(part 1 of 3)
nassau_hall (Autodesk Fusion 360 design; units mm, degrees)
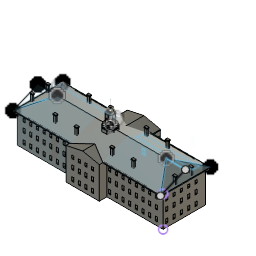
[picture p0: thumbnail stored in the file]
description: Open CASCADE Model
part number: Open CASCADE STEP translator 7.8 1
description: Part Number
part number: Open CASCADE STEP translator 7.8 1.1
part number: 2026-04-23-23-28-18-943
parameter "d279" = 0
base_feature "Base Feature1"
delete_face "DeleteFace1"
delete_face "DeleteFace2"
delete_face "DeleteFace3"
delete_face "DeleteFace4"
delete_face "DeleteFace5"
delete_face "DeleteFace6"
position "Position1"
extrude "Extrude1" add of existing geometry blind 100
extrude "Extrude2" add of existing geometry blind 2.5
extrude "Extrude3" add of existing geometry blind 2.5
extrude "Extrude4" add of existing geometry blind 2.5
extrude "Extrude5" add of existing geometry blind 2.5
extrude "Extrude6" add of existing geometry blind 2.5
extrude "Extrude7" add of existing geometry blind 2.5
sketch "Sketch1" plane through (-7.6571, 5.2611, 13.1142) normal (0, 1, 0) x axis (1, 0, 0)
split "Split1"
copy_paste_bodies "CopyPasteBodies1"
move "Move1"
move "Move2"
split "Split1"
extrude "Extrude1" add of existing geometry blind 92
delete_face "DeleteFace1"
delete_face "DeleteFace2"
extrude "Extrude8" add of existing geometry blind 30
extrude "Extrude9" add of existing geometry blind 1
extrude "Extrude2" add of existing geometry blind 30
split "Split2"
extrude "Extrude10" add of existing geometry blind 5
extrude "Extrude11" add of existing geometry blind 5
split "Split3"
move "Move1"
remove_body "RemoveBody1"
split "Split4"
delete_face "DeleteFace3"
split "Split5"
sketch "Sketch2" plane through (0, 0, 0) normal (0, 0, 1) x axis (1, 0, 0)
sketch "Sketch3" plane through (0, 0, 0) normal (0, 0, 1) x axis (1, 0, 0)
sketch "Sketch4" plane through (0, 0, 0) normal (0, 0, 1) x axis (1, 0, 0)
  line L1 (269.0284, 15.4255) -> (242.8779, 8.6742)
  line L2 (276.2569, 41.4481) -> (269.0284, 15.4255)
  line L3 (257.3349, 60.7195) -> (276.2569, 41.4481)
  line L4 (231.1844, 53.9682) -> (257.3349, 60.7195)
  line L5 (223.9559, 27.9456) -> (231.1844, 53.9682)
  line L6 (242.8779, 8.6742) -> (223.9559, 27.9456)
sketch "Sketch5" plane through (0, 0, 0) normal (0, 0, 1) x axis (1, 0, 0)
  line L1 (251.8031, 71.6805) -> (256.2642, 61.9825)
  line L2 (241.7911, 75.3836) -> (251.8031, 71.6805)
  line L3 (232.093, 70.9224) -> (241.7911, 75.3836)
  line L4 (228.39, 60.9104) -> (232.093, 70.9224)
  line L5 (232.8511, 51.2123) -> (228.39, 60.9104)
  line L6 (242.8632, 47.5093) -> (232.8511, 51.2123)
  line L7 (252.5612, 51.9704) -> (242.8632, 47.5093)
  line L8 (256.2642, 61.9825) -> (252.5612, 51.9704)
extrude "Extrude12" cut of existing geometry blind -80
extrude "Extrude5" cut of existing geometry blind -80
extrude "Extrude13" add of existing geometry blind 25
extrude "Extrude14" add of existing geometry blind 25
extrude "Extrude15" add of existing geometry blind 25
extrude "Extrude16" add of existing geometry blind 25
extrude "Extrude17" add of existing geometry blind 25
extrude "Extrude18" add of existing geometry blind 25
sketch "Sketch6" plane through (0, 19.3945, 0) normal (0, 1, 0) x axis (-1, 0, 0)
  line L1 (167.5476, -14.3624) -> (41.0476, -14.3624)
  line L2 (167.5476, 55.1376) -> (167.5476, -14.3624)
  line L3 (164.5476, 55.1376) -> (167.5476, 55.1376)
  line L4 (137.5476, 55.1376) -> (164.5476, 55.1376)
  line L5 (137.5476, 57.1376) -> (137.5476, 55.1376)
  line L6 (41.0476, 57.1376) -> (137.5476, 57.1376)
  line L7 (41.0476, -14.3624) -> (41.0476, 57.1376)
  line L8 (49.5073, 26) -> (45, 26)
  line L9 (49.5073, 17) -> (49.5073, 26)
  line L10 (45, 17) -> (49.5073, 17)
  line L11 (45, 26) -> (45, 17)
  horizontal L8
  vertical L9
  horizontal L10
  vertical L11
extrude "Extrude19" cut sketch "Sketch6" profile of L8 L9 L10 L11 against normal blind 15
sketch "Sketch7" plane through (0, 4.3945, 0) normal (0, 1, 0) x axis (-1, 0, 0)
  line L1 (49.5073, 17) -> (45, 17)
  line L2 (49.5073, 26) -> (49.5073, 17)
  line L3 (45, 26) -> (49.5073, 26)
  line L4 (45, 17) -> (45, 26)
sketch "Sketch8" plane through (0, 19.3945, 0) normal (0, 1, 0) x axis (-1, 0, 0)
  line L1 (49.5073, 17) -> (49.5073, 26)
  line L2 (45, 17) -> (49.5073, 17)
  line L3 (45, 26) -> (45, 17)
  line L4 (49.5073, 26) -> (45, 26)
  line L5 (167.5476, -14.3624) -> (41.0476, -14.3624)
  line L6 (167.5476, 55.1376) -> (167.5476, -14.3624)
  line L7 (164.5476, 55.1376) -> (167.5476, 55.1376)
  line L8 (137.5476, 55.1376) -> (164.5476, 55.1376)
  line L9 (137.5476, 57.1376) -> (137.5476, 55.1376)
  line L10 (41.0476, 57.1376) -> (137.5476, 57.1376)
  line L11 (41.0476, -14.3624) -> (41.0476, 57.1376)
  line L12 (49.5133, 3) -> (45, 3)
  line L13 (49.5133, -6) -> (49.5133, 3)
  line L14 (45, -6) -> (49.5133, -6)
  line L15 (45, 3) -> (45, -6)
  horizontal L12
  vertical L13
  horizontal L14
  vertical L15
sketch "Sketch9" plane through (0, 19.3945, 0) normal (0, 1, 0) x axis (-1, 0, 0)
sketch "Sketch10" plane through (0, 19.3945, 0) normal (0, 1, 0) x axis (-1, 0, 0)
  line L1 (64.5, 3) -> (60, 3)
  line L2 (64.5, -6) -> (64.5, 3)
  line L3 (60, -6) -> (64.5, -6)
  line L4 (60, 3) -> (60, -6)
  line L5 (79.5, 3) -> (75, 3)
  line L6 (79.5, -6) -> (79.5, 3)
  line L7 (75, -6) -> (79.5, -6)
  line L8 (75, 3) -> (75, -6)
  line L9 (94.5, 3) -> (90, 3)
  line L10 (94.5, -6) -> (94.5, 3)
  line L11 (90, -6) -> (94.5, -6)
  line L12 (90, 3) -> (90, -6)
  line L13 (109.5, 3) -> (105, 3)
  line L14 (109.5, -6) -> (109.5, 3)
  line L15 (105, -6) -> (109.5, -6)
  line L16 (105, 3) -> (105, -6)
  line L17 (124.5, 3) -> (120, 3)
  line L18 (124.5, -6) -> (124.5, 3)
  line L19 (120, -6) -> (124.5, -6)
  line L20 (120, 3) -> (120, -6)
  line L21 (139.5, 3) -> (135, 3)
  line L22 (139.5, -6) -> (139.5, 3)
  line L23 (135, -6) -> (139.5, -6)
  line L24 (135, 3) -> (135, -6)
  line L25 (154.5, 3) -> (150, 3)
  line L26 (154.5, -6) -> (154.5, 3)
  line L27 (150, -6) -> (154.5, -6)
  line L28 (150, 3) -> (150, -6)
  line L29 (64.5, 26) -> (60, 26)
  line L30 (64.5, 17) -> (64.5, 26)
  line L31 (60, 17) -> (64.5, 17)
  line L32 (60, 26) -> (60, 17)
  line L33 (79.5, 26) -> (75, 26)
  line L34 (79.5, 17) -> (79.5, 26)
  line L35 (75, 17) -> (79.5, 17)
  line L36 (75, 26) -> (75, 17)
  line L37 (94.5, 26) -> (90, 26)
  line L38 (94.5, 17) -> (94.5, 26)
  line L39 (90, 17) -> (94.5, 17)
  line L40 (90, 26) -> (90, 17)
  line L41 (109.5, 26) -> (105, 26)
  line L42 (109.5, 17) -> (109.5, 26)
  line L43 (105, 17) -> (109.5, 17)
  line L44 (105, 26) -> (105, 17)
  line L45 (124.5, 26) -> (120, 26)
  line L46 (124.5, 17) -> (124.5, 26)
  line L47 (120, 17) -> (124.5, 17)
  line L48 (120, 26) -> (120, 17)
  line L49 (139.5, 26) -> (135, 26)
  line L50 (139.5, 17) -> (139.5, 26)
  line L51 (135, 17) -> (139.5, 17)
  line L52 (135, 26) -> (135, 17)
  line L53 (154.5, 26) -> (150, 26)
  line L54 (154.5, 17) -> (154.5, 26)
  line L55 (150, 17) -> (154.5, 17)
  line L56 (150, 26) -> (150, 17)
  horizontal L1
  vertical L2
  horizontal L3
  vertical L4
  horizontal L5
  vertical L6
  horizontal L7
  vertical L8
  horizontal L9
  vertical L10
  horizontal L11
  vertical L12
  horizontal L13
  vertical L14
  horizontal L15
  vertical L16
  horizontal L17
  vertical L18
  horizontal L19
  vertical L20
  horizontal L21
  vertical L22
  horizontal L23
  vertical L24
  horizontal L25
  vertical L26
  horizontal L27
  vertical L28
  horizontal L29
  vertical L30
  horizontal L31
  vertical L32
  horizontal L33
  vertical L34
  horizontal L35
  vertical L36
  horizontal L37
  vertical L38
  horizontal L39
  vertical L40
  horizontal L41
  vertical L42
  horizontal L43
  vertical L44
  horizontal L45
  vertical L46
  horizontal L47
  vertical L48
  horizontal L49
  vertical L50
  horizontal L51
  vertical L52
  horizontal L53
  vertical L54
  horizontal L55
  vertical L56
extrude "Extrude20" cut sketch "Sketch10" + "Sketch8" profile of S2:L1 S2:L2 S2:L3 S2:L4 S2:L12 S2:L13 S2:L14 S2:L15 S1:L1 S1:L2 S1:L3 S1:L4 S1:L5 S1:L6 S1:L7 S1:L8 S1:L9 S1:L10 S1:L11 S1:L12 S1:L13 S1:L14 S1:L15 S1:L16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 blind -13
extrude "Extrude21" cut of existing geometry blind -13
sketch "Sketch11" plane through (0, 19.3945, 0) normal (0, 1, 0) x axis (-1, 0, 0)
  line L1 (49.5133, -6) -> (49.5133, 3)
  line L2 (45, -6) -> (49.5133, -6)
  line L3 (45, 3) -> (45, -6)
  line L4 (49.5133, 3) -> (45, 3)
  line L5 (154.5, -6) -> (154.5, 3)
  line L6 (150, -6) -> (154.5, -6)
  line L7 (150, 3) -> (150, -6)
  line L8 (154.5, 3) -> (150, 3)
  line L9 (109.5, 17) -> (109.5, 26)
  line L10 (105, 17) -> (109.5, 17)
  line L11 (105, 26) -> (105, 17)
  line L12 (109.5, 26) -> (105, 26)
  line L13 (79.5, -6) -> (79.5, 3)
  line L14 (75, -6) -> (79.5, -6)
  line L15 (75, 3) -> (75, -6)
  line L16 (79.5, 3) -> (75, 3)
  line L17 (64.5, 17) -> (64.5, 26)
  line L18 (60, 17) -> (64.5, 17)
  line L19 (60, 26) -> (60, 17)
  line L20 (64.5, 26) -> (60, 26)
  line L21 (94.5, 17) -> (94.5, 26)
  line L22 (90, 17) -> (94.5, 17)
  line L23 (90, 26) -> (90, 17)
  line L24 (94.5, 26) -> (90, 26)
  line L25 (124.5, 17) -> (124.5, 26)
  line L26 (120, 17) -> (124.5, 17)
  line L27 (120, 26) -> (120, 17)
  line L28 (124.5, 26) -> (120, 26)
  line L29 (124.5, -6) -> (124.5, 3)
  line L30 (120, -6) -> (124.5, -6)
  line L31 (120, 3) -> (120, -6)
  line L32 (124.5, 3) -> (120, 3)
  line L33 (154.5, 17) -> (154.5, 26)
  line L34 (150, 17) -> (154.5, 17)
  line L35 (150, 26) -> (150, 17)
  line L36 (154.5, 26) -> (150, 26)
  line L37 (109.5, -6) -> (109.5, 3)
  line L38 (105, -6) -> (109.5, -6)
  line L39 (105, 3) -> (105, -6)
  line L40 (109.5, 3) -> (105, 3)
  line L41 (79.5, 17) -> (79.5, 26)
  line L42 (75, 17) -> (79.5, 17)
  line L43 (75, 26) -> (75, 17)
  line L44 (79.5, 26) -> (75, 26)
  line L45 (64.5, -6) -> (64.5, 3)
  line L46 (60, -6) -> (64.5, -6)
  line L47 (60, 3) -> (60, -6)
  line L48 (64.5, 3) -> (60, 3)
  line L49 (94.5, -6) -> (94.5, 3)
  line L50 (90, -6) -> (94.5, -6)
  line L51 (90, 3) -> (90, -6)
  line L52 (94.5, 3) -> (90, 3)
  line L53 (139.5, 17) -> (139.5, 26)
  line L54 (135, 17) -> (139.5, 17)
  line L55 (135, 26) -> (135, 17)
  line L56 (139.5, 26) -> (135, 26)
  line L57 (139.5, -6) -> (139.5, 3)
  line L58 (135, -6) -> (139.5, -6)
  line L59 (135, 3) -> (135, -6)
  line L60 (139.5, 3) -> (135, 3)
  line L61 (49.5073, 17) -> (49.5073, 26)
  line L62 (45, 17) -> (49.5073, 17)
  line L63 (45, 26) -> (45, 17)
  line L64 (49.5073, 26) -> (45, 26)
  line L65 (167.5476, -14.3624) -> (41.0476, -14.3624)
  line L66 (167.5476, 55.1376) -> (167.5476, -14.3624)
  line L67 (164.5476, 55.1376) -> (167.5476, 55.1376)
  line L68 (137.5476, 55.1376) -> (164.5476, 55.1376)
  line L69 (137.5476, 57.1376) -> (137.5476, 55.1376)
  line L70 (41.0476, 57.1376) -> (137.5476, 57.1376)
  line L71 (41.0476, -14.3624) -> (41.0476, 57.1376)
  line L72 (49.5, 45) -> (45, 45)
  line L73 (49.5, 38) -> (49.5, 45)
  line L74 (45, 38) -> (49.5, 38)
  line L75 (45, 45) -> (45, 38)
  line L76 (64.5, 45) -> (60, 45)
  line L77 (64.5, 38) -> (64.5, 45)
  line L78 (60, 38) -> (64.5, 38)
  line L79 (60, 45) -> (60, 38)
  line L80 (79.5, 45) -> (75, 45)
  line L81 (79.5, 38) -> (79.5, 45)
  line L82 (75, 38) -> (79.5, 38)
  line L83 (75, 45) -> (75, 38)
  line L84 (94.5, 45) -> (90, 45)
  line L85 (94.5, 38) -> (94.5, 45)
  line L86 (90, 38) -> (94.5, 38)
  line L87 (90, 45) -> (90, 38)
  line L88 (109.5, 45) -> (105, 45)
  line L89 (109.5, 38) -> (109.5, 45)
  line L90 (105, 38) -> (109.5, 38)
  line L91 (105, 45) -> (105, 38)
  line L92 (124.5, 45) -> (120, 45)
  line L93 (124.5, 38) -> (124.5, 45)
  line L94 (120, 38) -> (124.5, 38)
  line L95 (120, 45) -> (120, 38)
  line L96 (139.5, 45) -> (135, 45)
  line L97 (139.5, 38) -> (139.5, 45)
  line L98 (135, 38) -> (139.5, 38)
  line L99 (135, 45) -> (135, 38)
  line L100 (154.5, 45) -> (150, 45)
  line L101 (154.5, 38) -> (154.5, 45)
  line L102 (150, 38) -> (154.5, 38)
  line L103 (150, 45) -> (150, 38)
  horizontal L72
  vertical L73
  horizontal L74
  vertical L75
  horizontal L76
  vertical L77
  horizontal L78
  vertical L79
  horizontal L80
  vertical L81
  horizontal L82
  vertical L83
  horizontal L84
  vertical L85
  horizontal L86
  vertical L87
  horizontal L88
  vertical L89
  horizontal L90
  vertical L91
  horizontal L92
  vertical L93
  horizontal L94
  vertical L95
  horizontal L96
  vertical L97
  horizontal L98
  vertical L99
  horizontal L100
  vertical L101
  horizontal L102
  vertical L103
extrude "Extrude22" cut sketch "Sketch11" profile of L72 L73 L74 L75 L76 L77 L78 L79 L80 L81 L82 L83 L84 L85 L86 L87 L88 L89 L90 L91 L92 L93 L94 L95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 against normal blind 13
extrude "Extrude23" cut of existing geometry blind -4
extrude "Extrude24" add of existing geometry blind 20
sketch "Sketch12" plane through (-167.5476, 0, 0) normal (-1, 0, 0) x axis (0, -1, 0)
  line L1 (63.1055, -14.3624) -> (-19.3945, -14.3624)
  line L2 (63.1055, 55.1376) -> (63.1055, -14.3624)
  line L3 (-19.3945, 55.1376) -> (63.1055, 55.1376)
  line L4 (-19.3945, -14.3624) -> (-19.3945, 55.1376)
  line L5 (-8.5, 45) -> (-13, 45)
  line L6 (-8.5, 38) -> (-8.5, 45)
  line L7 (-13, 38) -> (-8.5, 38)
  line L8 (-13, 45) -> (-13, 38)
  line L9 (6.5, 45) -> (2, 45)
  line L10 (6.5, 38) -> (6.5, 45)
  line L11 (2, 38) -> (6.5, 38)
  line L12 (2, 45) -> (2, 38)
  line L13 (21.5, 45) -> (17, 45)
  line L14 (21.5, 38) -> (21.5, 45)
  line L15 (17, 38) -> (21.5, 38)
  line L16 (17, 45) -> (17, 38)
  line L17 (36.5, 45) -> (32, 45)
  line L18 (36.5, 38) -> (36.5, 45)
  line L19 (32, 38) -> (36.5, 38)
  line L20 (32, 45) -> (32, 38)
  line L21 (51.5, 45) -> (47, 45)
  line L22 (51.5, 38) -> (51.5, 45)
  line L23 (47, 38) -> (51.5, 38)
  line L24 (47, 45) -> (47, 38)
  line L25 (-8.5, 26) -> (-13, 26)
  line L26 (-8.5, 17) -> (-8.5, 26)
  line L27 (-13, 17) -> (-8.5, 17)
  line L28 (-13, 26) -> (-13, 17)
  line L29 (6.5, 26) -> (2, 26)
  line L30 (6.5, 17) -> (6.5, 26)
  line L31 (2, 17) -> (6.5, 17)
  line L32 (2, 26) -> (2, 17)
  line L33 (21.5, 26) -> (17, 26)
  line L34 (21.5, 17) -> (21.5, 26)
  line L35 (17, 17) -> (21.5, 17)
  line L36 (17, 26) -> (17, 17)
  line L37 (36.5, 26) -> (32, 26)
  line L38 (36.5, 17) -> (36.5, 26)
  line L39 (32, 17) -> (36.5, 17)
  line L40 (32, 26) -> (32, 17)
  line L41 (51.5, 26) -> (47, 26)
  line L42 (51.5, 17) -> (51.5, 26)
  line L43 (47, 17) -> (51.5, 17)
  line L44 (47, 26) -> (47, 17)
  horizontal L5
  vertical L6
  horizontal L7
  vertical L8
  horizontal L9
  vertical L10
  horizontal L11
  vertical L12
  horizontal L13
  vertical L14
  horizontal L15
  vertical L16
  horizontal L17
  vertical L18
  horizontal L19
  vertical L20
  horizontal L21
  vertical L22
  horizontal L23
  vertical L24
  horizontal L25
  vertical L26
  horizontal L27
  vertical L28
  horizontal L29
  vertical L30
  horizontal L31
  vertical L32
  horizontal L33
  vertical L34
  horizontal L35
  vertical L36
  horizontal L37
  vertical L38
  horizontal L39
  vertical L40
  horizontal L41
  vertical L42
  horizontal L43
  vertical L44
sketch "Sketch13" plane through (-167.5476, 0, 0) normal (-1, 0, 0) x axis (0, -1, 0)
  line L1 (-8.5, 3) -> (-13, 3)
  line L2 (-8.5, -6) -> (-8.5, 3)
  line L3 (-13, -6) -> (-8.5, -6)
  line L4 (-13, 3) -> (-13, -6)
  line L5 (6.5, 3) -> (2, 3)
  line L6 (6.5, -6) -> (6.5, 3)
  line L7 (2, -6) -> (6.5, -6)
  line L8 (2, 3) -> (2, -6)
  line L9 (21.5, 3) -> (17, 3)
  line L10 (21.5, -6) -> (21.5, 3)
  line L11 (17, -6) -> (21.5, -6)
  line L12 (17, 3) -> (17, -6)
  line L13 (36.5, 3) -> (32, 3)
  line L14 (36.5, -6) -> (36.5, 3)
  line L15 (32, -6) -> (36.5, -6)
  line L16 (32, 3) -> (32, -6)
  line L17 (51.5, 3) -> (47, 3)
  line L18 (51.5, -6) -> (51.5, 3)
  line L19 (47, -6) -> (51.5, -6)
  line L20 (47, 3) -> (47, -6)
  horizontal L1
  vertical L2
  horizontal L3
  vertical L4
  horizontal L5
  vertical L6
  horizontal L7
  vertical L8
  horizontal L9
  vertical L10
  horizontal L11
  vertical L12
  horizontal L13
  vertical L14
  horizontal L15
  vertical L16
  horizontal L17
  vertical L18
  horizontal L19
  vertical L20
extrude "Extrude25" cut sketch "Sketch12" + "Sketch13" profile of S1:L5 S1:L6 S1:L7 S1:L8 S1:L9 S1:L10 S1:L11 S1:L12 S1:L13 S1:L14 S1:L15 S1:L16 S1:L17 S1:L18 S1:L19 S1:L20 S1:L21 S1:L22 S1:L23 S1:L24 S1:L25 S1:L26 S1:L27 S1:L28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 blind -13
extrude "Extrude26" add of existing geometry blind 4
extrude "Extrude27" add of existing geometry blind 4
extrude "Extrude28" add of existing geometry blind 2
sketch "Sketch14" plane through (0, 19.3945, 0) normal (0, 1, 0) x axis (-1, 0, 0)
  line L1 (-33.9524, -14.3624) -> (-160.4524, -14.3624)
  line L2 (-33.9524, 57.1376) -> (-33.9524, -14.3624)
  line L3 (-130.4524, 57.1376) -> (-33.9524, 57.1376)
  line L4 (-130.4524, 55.1376) -> (-130.4524, 57.1376)
  line L5 (-160.4524, 55.1376) -> (-130.4524, 55.1376)
  line L6 (-160.4524, -14.3624) -> (-160.4524, 55.1376)
  line L7 (-42.5, 45) -> (-38, 45)
  line L8 (-42.5, 38) -> (-42.5, 45)
  line L9 (-38, 38) -> (-42.5, 38)
  line L10 (-38, 45) -> (-38, 38)
  line L11 (-57.5, 45) -> (-53, 45)
  line L12 (-57.5, 38) -> (-57.5, 45)
  line L13 (-53, 38) -> (-57.5, 38)
  line L14 (-53, 45) -> (-53, 38)
  line L15 (-72.5, 45) -> (-68, 45)
  line L16 (-72.5, 38) -> (-72.5, 45)
  line L17 (-68, 38) -> (-72.5, 38)
  line L18 (-68, 45) -> (-68, 38)
  line L19 (-87.5, 45) -> (-83, 45)
  line L20 (-87.5, 38) -> (-87.5, 45)
  line L21 (-83, 38) -> (-87.5, 38)
  line L22 (-83, 45) -> (-83, 38)
  line L23 (-102.5, 45) -> (-98, 45)
  line L24 (-102.5, 38) -> (-102.5, 45)
  line L25 (-98, 38) -> (-102.5, 38)
  line L26 (-98, 45) -> (-98, 38)
  line L27 (-117.5, 45) -> (-113, 45)
  line L28 (-117.5, 38) -> (-117.5, 45)
  line L29 (-113, 38) -> (-117.5, 38)
  line L30 (-113, 45) -> (-113, 38)
  line L31 (-132.5, 45) -> (-128, 45)
  line L32 (-132.5, 38) -> (-132.5, 45)
  line L33 (-128, 38) -> (-132.5, 38)
  line L34 (-128, 45) -> (-128, 38)
  line L35 (-147.5, 45) -> (-143, 45)
  line L36 (-147.5, 38) -> (-147.5, 45)
  line L37 (-143, 38) -> (-147.5, 38)
  line L38 (-143, 45) -> (-143, 38)
  line L39 (-42.5, 26) -> (-38, 26)
  line L40 (-42.5, 17) -> (-42.5, 26)
  line L41 (-38, 17) -> (-42.5, 17)
  line L42 (-38, 26) -> (-38, 17)
  line L43 (-57.5, 26) -> (-53, 26)
  line L44 (-57.5, 17) -> (-57.5, 26)
  line L45 (-53, 17) -> (-57.5, 17)
  line L46 (-53, 26) -> (-53, 17)
  line L47 (-72.5, 26) -> (-68, 26)
  line L48 (-72.5, 17) -> (-72.5, 26)
  line L49 (-68, 17) -> (-72.5, 17)
  line L50 (-68, 26) -> (-68, 17)
  line L51 (-87.5, 26) -> (-83, 26)
  line L52 (-87.5, 17) -> (-87.5, 26)
  line L53 (-83, 17) -> (-87.5, 17)
  line L54 (-83, 26) -> (-83, 17)
  line L55 (-102.5, 26) -> (-98, 26)
  line L56 (-102.5, 17) -> (-102.5, 26)
  line L57 (-98, 17) -> (-102.5, 17)
  line L58 (-98, 26) -> (-98, 17)
  line L59 (-117.5, 26) -> (-113, 26)
  line L60 (-117.5, 16.9958) -> (-117.5, 26)
  line L61 (-113, 16.9958) -> (-117.5, 16.9958)
  line L62 (-113, 26) -> (-113, 16.9958)
  horizontal L7
  vertical L8
  horizontal L9
  vertical L10
  horizontal L11
  vertical L12
  horizontal L13
  vertical L14
  horizontal L15
  vertical L16
  horizontal L17
  vertical L18
  horizontal L19
  vertical L20
  horizontal L21
  vertical L22
  horizontal L23
  vertical L24
  horizontal L25
  vertical L26
  horizontal L27
  vertical L28
  horizontal L29
  vertical L30
  horizontal L31
  vertical L32
  horizontal L33
  vertical L34
  horizontal L35
  vertical L36
  horizontal L37
  vertical L38
  horizontal L39
  vertical L40
  horizontal L41
  vertical L42
  horizontal L43
  vertical L44
  horizontal L45
  vertical L46
  horizontal L47
  vertical L48
  horizontal L49
  vertical L50
  horizontal L51
  vertical L52
  horizontal L53
  vertical L54
  horizontal L55
  vertical L56
  horizontal L57
  vertical L58
  horizontal L59
  vertical L60
  horizontal L61
  vertical L62
sketch "Sketch15" plane through (0, 19.3945, 0) normal (0, 1, 0) x axis (-1, 0, 0)
  line L1 (-132.5, 26) -> (-128, 26)
  line L2 (-132.5, 17) -> (-132.5, 26)
  line L3 (-128, 17) -> (-132.5, 17)
  line L4 (-128, 26) -> (-128, 17)
  line L5 (-147.5, 26) -> (-143, 26)
  line L6 (-147.5, 17) -> (-147.5, 26)
  line L7 (-143, 17) -> (-147.5, 17)
  line L8 (-143, 26) -> (-143, 17)
  line L9 (-42.5323, 3) -> (-38, 3)
  line L10 (-42.5323, -6.0191) -> (-42.5323, 3)
  line L11 (-38, -6.0191) -> (-42.5323, -6.0191)
  line L12 (-38, 3) -> (-38, -6.0191)
  line L13 (-57.5, 3) -> (-53, 3)
  line L14 (-57.5, -6) -> (-57.5, 3)
  line L15 (-53, -6) -> (-57.5, -6)
  line L16 (-53, 3) -> (-53, -6)
  line L17 (-72.5, 3) -> (-68, 3)
  line L18 (-72.5, -6) -> (-72.5, 3)
  line L19 (-68, -6) -> (-72.5, -6)
  line L20 (-68, 3) -> (-68, -6)
  line L21 (-87.5, 3) -> (-83, 3)
  line L22 (-87.5, -6) -> (-87.5, 3)
  line L23 (-83, -6) -> (-87.5, -6)
  line L24 (-83, 3) -> (-83, -6)
  line L25 (-102.5, 3) -> (-98, 3)
  line L26 (-102.5, -6) -> (-102.5, 3)
  line L27 (-98, -6) -> (-102.5, -6)
  line L28 (-98, 3) -> (-98, -6)
  line L29 (-117.5, 3) -> (-113, 3)
  line L30 (-117.5, -6) -> (-117.5, 3)
  line L31 (-113, -6) -> (-117.5, -6)
  line L32 (-113, 3) -> (-113, -6)
  line L33 (-132.5, 3) -> (-128, 3)
  line L34 (-132.5, -6) -> (-132.5, 3)
  line L35 (-128, -6) -> (-132.5, -6)
  line L36 (-128, 3) -> (-128, -6)
  line L37 (-147.5, 3) -> (-143, 3)
  line L38 (-147.5, -6) -> (-147.5, 3)
  line L39 (-143, -6) -> (-147.5, -6)
  line L40 (-143, 3) -> (-143, -6)
  horizontal L1
  vertical L2
  horizontal L3
  vertical L4
  horizontal L5
  vertical L6
  horizontal L7
  vertical L8
  horizontal L9
  vertical L10
  horizontal L11
  vertical L12
  horizontal L13
  vertical L14
  horizontal L15
  vertical L16
  horizontal L17
  vertical L18
  horizontal L19
  vertical L20
  horizontal L21
  vertical L22
  horizontal L23
  vertical L24
  horizontal L25
  vertical L26
  horizontal L27
  vertical L28
  horizontal L29
  vertical L30
  horizontal L31
  vertical L32
  horizontal L33
  vertical L34
  horizontal L35
  vertical L36
  horizontal L37
  vertical L38
  horizontal L39
  vertical L40
sketch "Sketch16" plane through (0, -63.1055, 0) normal (0, -1, 0) x axis (1, 0, 0)
  line L1 (160.4524, -14.3624) -> (33.9524, -14.3624)
  line L2 (130.4524, 55.1376) -> (160.4524, 55.1376)
  line L3 (130.4524, 57.1376) -> (130.4524, 55.1376)
  line L4 (33.9524, 57.1376) -> (130.4524, 57.1376)
  line L5 (33.9524, -14.3624) -> (33.9524, 57.1376)
form "Form1"
sketch "Sketch17" plane through (0, 0, 0) normal (0, 0, 1) x axis (1, 0, 0)
  line L1 (-10.0564, 79.0939) -> (-14.8227, 89.3992)
  line L2 (0.6008, 75.1773) -> (-10.0564, 79.0939)
  line L3 (10.9061, 79.9436) -> (0.6008, 75.1773)
  line L4 (14.8227, 90.6008) -> (10.9061, 79.9436)
  line L5 (10.0564, 100.9061) -> (14.8227, 90.6008)
  line L6 (-0.6008, 104.8227) -> (10.0564, 100.9061)
  line L7 (-10.9061, 100.0564) -> (-0.6008, 104.8227)
  line L8 (-14.8227, 89.3992) -> (-10.9061, 100.0564)
extrude "Extrude6" new body sketch "Sketch17" along normal blind 10
move_face "MoveFace1"
extrude "Extrude7" cut of existing geometry blind -3
extrude "Extrude8" cut of existing geometry blind -2
extrude "Extrude9" add of existing geometry blind 2
sketch "Sketch18" plane through (0, 0, 81) normal (0, 0, 1) x axis (-1, 0, 0)
  line L1 (19.0238, 21.5031) -> (18.9883, 10.1491)
  line L2 (11.0203, 29.5567) -> (19.0238, 21.5031)
  line L3 (-0.3337, 29.5921) -> (11.0203, 29.5567)
  line L4 (-8.3873, 21.5887) -> (-0.3337, 29.5921)
  line L5 (-8.4227, 10.2346) -> (-8.3873, 21.5887)
  line L6 (-0.4193, 2.181) -> (-8.4227, 10.2346)
  line L7 (10.9348, 2.1456) -> (-0.4193, 2.181)
  line L8 (18.9883, 10.1491) -> (10.9348, 2.1456)
  line L9 (10.509, 28.639) -> (17.9578, 21.1769)
  line L10 (-0.0347, 28.6483) -> (10.509, 28.639)
  line L11 (-7.4968, 21.1995) -> (-0.0347, 28.6483)
  line L12 (-7.5061, 10.6558) -> (-7.4968, 21.1995)
  line L13 (-0.0573, 3.1937) -> (-7.5061, 10.6558)
  line L14 (10.4864, 3.1844) -> (-0.0573, 3.1937)
  line L15 (17.9485, 10.6332) -> (10.4864, 3.1844)
  line L16 (17.9578, 21.1769) -> (17.9485, 10.6332)
extrude "Extrude10" add sketch "Sketch18" profile of L9 L10 L11 L12 L13 L14 L15 L16 along normal blind 2
sketch "Sketch19" plane through (0, 0, 83) normal (0, 0, 1) x axis (-1, 0, 0)
  line L1 (17.9578, 21.1769) -> (17.9485, 10.6332)
  line L2 (10.509, 28.639) -> (17.9578, 21.1769)
  line L3 (-0.0347, 28.6483) -> (10.509, 28.639)
  line L4 (-7.4968, 21.1995) -> (-0.0347, 28.6483)
  line L5 (-7.5061, 10.6558) -> (-7.4968, 21.1995)
  line L6 (-0.0573, 3.1937) -> (-7.5061, 10.6558)
  line L7 (10.4864, 3.1844) -> (-0.0573, 3.1937)
  line L8 (17.9485, 10.6332) -> (10.4864, 3.1844)
  line L9 (0.0503, 27.8062) -> (10, 28)
  line L10 (-6.8481, 20.6338) -> (0.0503, 27.8062)
  line L11 (-6.6544, 10.6841) -> (-6.8481, 20.6338)
  line L12 (0.5181, 3.7856) -> (-6.6544, 10.6841)
  line L13 (10.4678, 3.9794) -> (0.5181, 3.7856)
  line L14 (17.3662, 11.1519) -> (10.4678, 3.9794)
  line L15 (17.1725, 21.1015) -> (17.3662, 11.1519)
  line L16 (10, 28) -> (17.1725, 21.1015)
extrude "Extrude11" add sketch "Sketch19" profile of L9 L10 L11 L12 L13 L14 L15 L16 along normal blind 5
extrude "Extrude12" add of existing geometry blind 10
extrude "Extrude13" cut of existing geometry blind -12
sketch "Sketch20" plane through (0, 0, 86) normal (0, 0, 1) x axis (-1, 0, 0)
  line L1 (10, 28) -> (17.1725, 21.1015)
  line L2 (0.0503, 27.8062) -> (10, 28)
  line L3 (-6.8481, 20.6338) -> (0.0503, 27.8062)
  line L4 (-6.6544, 10.6841) -> (-6.8481, 20.6338)
  line L5 (0.5181, 3.7856) -> (-6.6544, 10.6841)
  line L6 (10.4678, 3.9794) -> (0.5181, 3.7856)
  line L7 (17.3662, 11.1519) -> (10.4678, 3.9794)
  line L8 (17.1725, 21.1015) -> (17.3662, 11.1519)
  line L9 (8.6097, 24.3477) -> (13.6119, 19.5101)
  line L10 (1.652, 24.2313) -> (8.6097, 24.3477)
  line L11 (-3.1856, 19.2291) -> (1.652, 24.2313)
  line L12 (-3.0692, 12.2714) -> (-3.1856, 19.2291)
  line L13 (1.933, 7.4338) -> (-3.0692, 12.2714)
  line L14 (8.8907, 7.5502) -> (1.933, 7.4338)
  line L15 (13.7283, 12.5524) -> (8.8907, 7.5502)
  line L16 (13.6119, 19.5101) -> (13.7283, 12.5524)
extrude "Extrude14" add sketch "Sketch20" profile of L9 L10 L11 L12 L13 L14 L15 L16 along normal blind 15
sketch "Sketch21" plane through (0, 0, 101) normal (0, 0, 1) x axis (-1, 0, 0)
  line L1 (13.6119, 19.5101) -> (13.7283, 12.5524)
  line L2 (8.6097, 24.3477) -> (13.6119, 19.5101)
  line L3 (1.652, 24.2313) -> (8.6097, 24.3477)
  line L4 (-3.1856, 19.2291) -> (1.652, 24.2313)
  line L5 (-3.0692, 12.2714) -> (-3.1856, 19.2291)
  line L6 (1.933, 7.4338) -> (-3.0692, 12.2714)
  line L7 (8.8907, 7.5502) -> (1.933, 7.4338)
  line L8 (13.7283, 12.5524) -> (8.8907, 7.5502)
  line L9 (12.7805, 19.3079) -> (13, 13)
  line L10 (8.165, 23.6131) -> (12.7805, 19.3079)
  line L11 (1.8571, 23.3937) -> (8.165, 23.6131)
  line L12 (-2.4481, 18.7781) -> (1.8571, 23.3937)
  line L13 (-2.2287, 12.4702) -> (-2.4481, 18.7781)
  line L14 (2.3869, 8.165) -> (-2.2287, 12.4702)
  line L15 (8.6948, 8.3844) -> (2.3869, 8.165)
  line L16 (13, 13) -> (8.6948, 8.3844)
extrude "Extrude15" cut sketch "Sketch21" profile of L9 L10 L11 L12 L13 L14 L15 L16 against normal blind 15
sketch "Sketch22" plane through (0.1238, -7.3994, 0) normal (-0.0167, 0.9999, 0) x axis (-0.9999, -0.0167, 0)
  line L1 (9.0158, 86) -> (2.0571, 86)
  line L2 (9.0158, 101) -> (9.0158, 86)
  line L3 (2.0571, 101) -> (9.0158, 101)
  line L4 (2.0571, 86) -> (2.0571, 101)
  line L5 (8, 97.5161) -> (3.0096, 97.5161)
  line L6 (8, 86) -> (8, 97.5161)
  line L7 (3.0096, 86) -> (8, 86)
  line L8 (3.0096, 97.5161) -> (3.0096, 86)
  circle C1 centre (5.5364, 97.5161) radius 2.5268
  point P9 (8, 86)
  point P7 (3.0096, 97.5161)
  horizontal L5
  vertical L6
  horizontal L7
  vertical L8
  coincident L1 P9
  coincident C1 P7
extrude "Extrude16" cut sketch "Sketch22" profile of L1 C1 L5 L6 L7 L8 against normal blind 2
sketch "Sketch23" plane through (-0.8211, 0.7941, 0) normal (-0.7188, 0.6952, 0) x axis (-0.6952, -0.7188, 0)
  line L1 (18.5668, 86) -> (11.608, 86)
  line L2 (18.5668, 101) -> (18.5668, 86)
  line L3 (11.608, 101) -> (18.5668, 101)
  line L4 (11.608, 86) -> (11.608, 101)
  line L5 (17.5, 97.5) -> (12.5, 97.5)
  line L6 (17.5, 86) -> (17.5, 97.5)
  line L7 (12.5, 86) -> (17.5, 86)
  line L8 (12.5, 97.5) -> (12.5, 86)
  circle C1 centre (15, 97.5) radius 2.5
  point P9 (17.5, 86)
  point P7 (12.5, 97.5)
  horizontal L5
  vertical L6
  horizontal L7
  vertical L8
  coincident L1 P9
  coincident C1 P7
extrude "Extrude17" cut sketch "Sketch23" profile of L1 C1 L5 L6 L7 L8 against normal blind 2
sketch "Sketch24" plane through (0, 0, -14.3624) normal (0, 0, -1) x axis (1, 0, 0)
  line L1 (33.9524, -19.3945) -> (33.9524, 63.1055)
  line L2 (160.4524, -19.3945) -> (33.9524, -19.3945)
  line L3 (160.4524, 63.1055) -> (160.4524, -19.3945)
  line L4 (33.9524, 63.1055) -> (160.4524, 63.1055)
  line L5 (-165.6279, -17.1616) -> (157.9638, -17.1616)
  line L6 (-165.6279, 61.1302) -> (-165.6279, -17.1616)
  line L7 (157.9638, 61.1302) -> (-165.6279, 61.1302)
  line L8 (157.9638, -17.1616) -> (157.9638, 61.1302)
  horizontal L5
  vertical L6
  horizontal L7
  vertical L8
extrude "Extrude29" cut sketch "Sketch24" profile of L1 L5 L7 L8 against normal blind 70
sketch "Sketch25" plane through (0, 0, -14.3624) normal (0, 0, -1) x axis (1, 0, 0)
  line L1 (-41.0476, 63.1055) -> (-41.0476, -19.3945)
  line L2 (-167.5476, 63.1055) -> (-41.0476, 63.1055)
  line L3 (-167.5476, -19.3945) -> (-167.5476, 63.1055)
  line L4 (-41.0476, -19.3945) -> (-167.5476, -19.3945)
  line L5 (-166, -18) -> (-43, -18)
  line L6 (-166, 61) -> (-166, -18)
  line L7 (-43, 61) -> (-166, 61)
  line L8 (-43, -18) -> (-43, 61)
  horizontal L5
  vertical L6
  horizontal L7
  vertical L8
extrude "Extrude30" add sketch "Sketch25" profile of L5 L6 L7 L8 along normal blind 70
extrude "Extrude31" cut of existing geometry blind -140
sketch "Sketch26" plane through (0, 0, -14.3624) normal (0, 0, -1) x axis (1, 0, 0)
  line L1 (33.9524, -57.3945) -> (-41.0476, -57.3945)
  line L2 (33.9524, 80.1055) -> (33.9524, -57.3945)
  line L3 (-41.0476, 80.1055) -> (33.9524, 80.1055)
  line L4 (-41.0476, -57.3945) -> (-41.0476, 80.1055)
  line L5 (-50, -17.0793) -> (33.9524, -17.0793)
  line L6 (-50, 61) -> (-50, -17.0793)
  line L7 (33.9524, 61) -> (-50, 61)
  line L8 (33.9524, -17.0793) -> (33.9524, 61)
  point P6 (33.9524, -17.0793)
  horizontal L5
  vertical L6
  horizontal L7
  vertical L8
  coincident L2 P6
extrude "Extrude32" cut sketch "Sketch26" profile of L2 L4 L5 L7 L8 against normal blind 70
sketch "Sketch27" plane through (0, 0, -14.3624) normal (0, 0, -1) x axis (1, 0, 0)
  line L1 (-43, -18) -> (-43, 61)
  line L2 (-166, -18) -> (-43, -18)
  line L3 (-166, 61) -> (-166, -18)
  line L4 (-43, 61) -> (-166, 61)
  line L5 (-41.0476, 63.1055) -> (-41.0476, -19.3945)
  line L6 (-167.5476, 63.1055) -> (-41.0476, 63.1055)
  line L7 (-167.5476, -19.3945) -> (-167.5476, 63.1055)
  line L8 (-41.0476, -19.3945) -> (-167.5476, -19.3945)
  line L9 (-43, -17.2714) -> (-41.0476, -17.2714)
  line L10 (-43, 61) -> (-43, -17.2714)
  line L11 (-41.0476, 61) -> (-43, 61)
  line L12 (-41.0476, -17.2714) -> (-41.0476, 61)
  point P2 (-43, 61)
  point P12 (-43, 61)
  point P10 (-41.0476, -17.2714)
  horizontal L9
  vertical L10
  horizontal L11
  vertical L12
  coincident P2 P12
  coincident L5 P10
extrude "Extrude33" cut sketch "Sketch27" profile of L1 L5 L9 L10 L11 L12 against normal blind 70
sketch "Sketch28" plane through (0, 0, -14.3624) normal (0, 0, -1) x axis (1, 0, 0)
  line L1 (-41.0476, -17.0793) -> (33.9524, -17.0793)
  line L2 (-41.0476, -57.3945) -> (-41.0476, -17.0793)
  line L3 (33.9524, -57.3945) -> (-41.0476, -57.3945)
  line L4 (33.9524, -17.0793) -> (33.9524, -57.3945)
  line L5 (-38.959, -19) -> (32, -19)
  line L6 (-38.959, -55.6025) -> (-38.959, -19)
  line L7 (32, -55.6025) -> (-38.959, -55.6025)
  line L8 (32, -19) -> (32, -55.6025)
  horizontal L5
  vertical L6
  horizontal L7
  vertical L8
extrude "Extrude18" cut sketch "Sketch28" profile of L5 L6 L7 L8 against normal blind 70
sketch "Sketch29" plane through (0, 0, -14.3624) normal (0, 0, -1) x axis (1, 0, 0)
  line L1 (32, -19) -> (-38.959, -19)
  line L2 (32, -55.6025) -> (32, -19)
  line L3 (-38.959, -55.6025) -> (32, -55.6025)
  line L4 (-38.959, -19) -> (-38.959, -55.6025)
  line L5 (-41.0476, -17.0793) -> (33.9524, -17.0793)
  line L6 (-41.0476, -57.3945) -> (-41.0476, -17.0793)
  line L7 (33.9524, -57.3945) -> (-41.0476, -57.3945)
  line L8 (33.9524, -17.0793) -> (33.9524, -57.3945)
  line L9 (-41.0476, -19) -> (33.9524, -19)
  line L10 (-41.0476, -17.0793) -> (-41.0476, -19)
  line L11 (33.9524, -17.0793) -> (-41.0476, -17.0793)
  line L12 (33.9524, -19) -> (33.9524, -17.0793)
  line L13 (-39.0985, -19) -> (32, -19)
  line L14 (-39.0985, -17.0793) -> (-39.0985, -19)
  line L15 (32, -17.0793) -> (-39.0985, -17.0793)
  line L16 (32, -19) -> (32, -17.0793)
  point P7 (-41.0476, -17.0793)
  point P12 (-41.0476, -17.0793)
  point P10 (33.9524, -19)
  point P16 (-39.0985, -17.0793)
  point P3 (32, -19)
  point P14 (32, -19)
  horizontal L9
  vertical L10
  horizontal L11
  vertical L12
  coincident P7 P12
  coincident L8 P10
  horizontal L13
  vertical L14
  horizontal L15
  vertical L16
  coincident L11 P16
  coincident P3 P14
extrude "Extrude35" cut sketch "Sketch29" profile of L1 L5 L9 L11 L13 L14 L15 L16 against normal blind 70
sketch "Sketch30" plane through (0, 0, -14.3624) normal (0, 0, -1) x axis (1, 0, 0)
  line L1 (33.9524, 61) -> (-41.0476, 61)
  line L2 (33.9524, 80.1055) -> (33.9524, 61)
  line L3 (-41.0476, 80.1055) -> (33.9524, 80.1055)
  line L4 (-41.0476, 61) -> (-41.0476, 80.1055)
  line L5 (-39, 61) -> (32, 61)
  line L6 (-39, 78) -> (-39, 61)
  line L7 (32, 78) -> (-39, 78)
  line L8 (32, 61) -> (32, 78)
  point P6 (32, 61)
  horizontal L5
  vertical L6
  horizontal L7
  vertical L8
  coincident L1 P6
extrude "Extrude36" add sketch "Sketch30" profile of L1 L5 L6 L7 L8 along normal blind 70
extrude "Extrude37" cut of existing geometry blind -140
sketch "Sketch31" plane through (-13.9344, -0.2331, 0) normal (-0.9999, -0.0167, 0) x axis (0.0167, -0.9999, 0)
  line L1 (19.2797, 86) -> (12.321, 86)
  line L2 (19.2797, 101) -> (19.2797, 86)
  line L3 (12.321, 101) -> (19.2797, 101)
  line L4 (12.321, 86) -> (12.321, 101)
  line L5 (18.2928, 97.5026) -> (13.17, 97.5026)
  line L6 (18.2928, 97.4946) -> (18.2928, 97.5026)
  line L7 (13.17, 97.4946) -> (18.2928, 97.4946)
  line L8 (13.17, 97.5026) -> (13.17, 97.4946)
  line L9 (18.2941, 97.5026) -> (13.17, 97.5026)
  line L10 (18.2941, 86) -> (18.2941, 97.5026)
  line L11 (13.17, 86) -> (18.2941, 86)
  line L12 (13.17, 97.5026) -> (13.17, 86)
  circle C1 centre (15.7314, 97.4946) radius 2.5614
  point P9 (18.2928, 97.4946)
  point P7 (13.17, 97.5026)
  point P12 (18.2941, 86)
  horizontal L5
  vertical L6
  horizontal L7
  vertical L8
  coincident C1 P9
  coincident C1 P7
  horizontal L9
  vertical L10
  horizontal L11
  vertical L12
  coincident L1 P12
extrude "Extrude19" cut sketch "Sketch31" profile of L1 C1 L5 L6 L7 L9 L10 L11 L12 against normal blind 2
extrude "Extrude20" cut of existing geometry blind -2
extrude "Extrude21" add of existing geometry blind 2
sketch "Sketch32" plane through (-16.3279, -16.8835, 0) normal (-0.6952, -0.7188, 0) x axis (0.7188, -0.6952, 0)
  line L1 (10.7371, 86) -> (3.7783, 86)
  line L2 (10.7371, 103) -> (10.7371, 86)
  line L3 (3.7783, 103) -> (10.7371, 103)
  line L4 (3.7783, 86) -> (3.7783, 103)
  line L5 (9.8041, 97.4857) -> (4.7124, 97.4857)
  line L6 (9.8041, 86) -> (9.8041, 97.4857)
  line L7 (4.7124, 86) -> (9.8041, 86)
  line L8 (4.7124, 97.4857) -> (4.7124, 86)
  circle C1 centre (7.2577, 97.5293) radius 2.5457
  point P9 (9.8041, 86)
  point P7 (4.7124, 97.4857)
  horizontal L5
  vertical L6
  horizontal L7
  vertical L8
  coincident L1 P9
  coincident C1 P7
extrude "Extrude22" cut sketch "Sketch32" profile of L1 C1 L5 L6 L7 L8 against normal blind 2
sketch "Sketch33" plane through (0.4048, -24.1969, 0) normal (0.0167, -0.9999, 0) x axis (0.9999, 0.0167, 0)
  line L1 (-2.0571, 86) -> (-9.0158, 86)
  line L2 (-2.0571, 103) -> (-2.0571, 86)
  line L3 (-9.0158, 103) -> (-2.0571, 103)
  line L4 (-9.0158, 86) -> (-9.0158, 103)
  line L5 (-3, 97.5131) -> (-8.0637, 97.5131)
  line L6 (-3, 86) -> (-3, 97.5131)
  line L7 (-8.0637, 86) -> (-3, 86)
  line L8 (-8.0637, 97.5131) -> (-8.0637, 86)
  circle C1 centre (-5.5364, 97.5156) radius 2.5273
  point P9 (-3, 86)
  point P7 (-8.0637, 97.5131)
  horizontal L5
  vertical L6
  horizontal L7
  vertical L8
  coincident L1 P9
  coincident C1 P7
extrude "Extrude23" cut sketch "Sketch33" profile of L1 C1 L5 L6 L7 L8 against normal blind 2
sketch "Sketch34" plane through (11.2553, -10.8849, 0) normal (0.7188, -0.6952, 0) x axis (0.6952, 0.7188, 0)
  line L1 (-11.608, 86) -> (-18.5668, 86)
  line L2 (-11.608, 103) -> (-11.608, 86)
  line L3 (-18.5668, 103) -> (-11.608, 103)
  line L4 (-18.5668, 86) -> (-18.5668, 103)
  line L5 (-12.55, 97.5038) -> (-17.6149, 97.5038)
  line L6 (-12.55, 86) -> (-12.55, 97.5038)
  line L7 (-17.6149, 86) -> (-12.55, 86)
  line L8 (-17.6149, 97.5038) -> (-17.6149, 86)
  circle C1 centre (-15.0874, 97.4919) radius 2.5275
  point P9 (-12.55, 86)
  point P7 (-17.6149, 97.5038)
  horizontal L5
  vertical L6
  horizontal L7
  vertical L8
  coincident L1 P9
  coincident C1 P7
  dimension "d121" diameter C1 = 5.055
extrude "Extrude24" cut sketch "Sketch34" profile of L1 C1 L5 L6 L7 L8 against normal blind 2
sketch "Sketch35" plane through (2.8631, 0.0479, 0) normal (0.9999, 0.0167, 0) x axis (-0.0167, 0.9999, 0)
  line L1 (-12.321, 86) -> (-19.2797, 86)
  line L2 (-12.321, 103) -> (-12.321, 86)
  line L3 (-19.2797, 103) -> (-12.321, 103)
  line L4 (-19.2797, 86) -> (-19.2797, 103)
  line L5 (-13.2793, 97.5157) -> (-18.3275, 97.5157)
  line L6 (-13.2793, 86) -> (-13.2793, 97.5157)
  line L7 (-18.3275, 86) -> (-13.2793, 86)
  line L8 (-18.3275, 97.5157) -> (-18.3275, 86)
  circle C1 centre (-15.8, 97.5) radius 2.5275
  point P9 (-13.2793, 86)
  point P7 (-18.3275, 97.5157)
  horizontal L5
  vertical L6
  horizontal L7
  vertical L8
  coincident L1 P9
  coincident C1 P7
  dimension "d124" diameter C1 = 5.055
extrude "Extrude25" cut sketch "Sketch35" profile of L1 C1 L5 L6 L7 L8 against normal blind 2
sketch "Sketch36" plane through (-4.649, -4.8072, 0) normal (0.6952, 0.7188, 0) x axis (-0.7188, 0.6952, 0)
  line L1 (-3.7783, 86) -> (-10.7371, 86)
  line L2 (-3.7783, 103) -> (-3.7783, 86)
  line L3 (-10.7371, 103) -> (-3.7783, 103)
  line L4 (-10.7371, 86) -> (-10.7371, 103)
  line L5 (-4.7, 97.5034) -> (-9.7775, 97.5034)
  line L6 (-4.7, 86) -> (-4.7, 97.5034)
  line L7 (-9.7775, 86) -> (-4.7, 86)
  line L8 (-9.7775, 97.5034) -> (-9.7775, 86)
  circle C1 centre (-7.25, 97.5) radius 2.5275
  point P9 (-4.7, 86)
  point P7 (-9.7775, 97.5034)
  horizontal L5
  vertical L6
  horizontal L7
  vertical L8
  coincident L1 P9
  coincident C1 P7
  dimension "d127" diameter C1 = 5.055
extrude "Extrude26" cut sketch "Sketch36" profile of L1 C1 L5 L6 L7 L8 against normal blind 2
sketch "Sketch37" plane through (0, 0, 0) normal (0, 1, 0) x axis (1, 0, 0)
  line L1 (-13.73, -103) -> (3.185, -103)
  line L2 (-13.73, -107.5) -> (-13.73, -103)
  line L3 (3.185, -107.5) -> (-13.73, -107.5)
  line L4 (3.185, -103) -> (3.185, -107.5)
  line L5 (-5.2725, -103) -> (-5.2725, -115.9575)
  arc A1 centre (-5.2725, -107.5) radius 8.4575 clockwise from (3.185, -107.5) to (-13.73, -107.5)
  point P7 (-5.2725, -115.9575)
  point P8 (-5.2725, -103)
  horizontal L1
  vertical L2
  horizontal L3
  vertical L4
  tangent L2 A1
  midpoint A1 P7
  midpoint L1 P8
delete_face "DeleteFace4"
extrude "Extrude27" new body sketch "Sketch37" profile of L3 A1 L5 along normal blind 0.1
revolve "Revolve1" AlongAngle 360
sketch "Sketch38" plane through (0, 0, 103) normal (0, 0, 1) x axis (-1, 0, 0)
  line L1 (-3.1856, 19.2291) -> (5.0727, 27.7684)
  line L2 (-3.0692, 12.2714) -> (-3.1856, 19.2291)
  line L3 (1.933, 7.4338) -> (-3.0692, 12.2714)
  line L4 (8.8907, 7.5502) -> (1.933, 7.4338)
  line L5 (13.7283, 12.5524) -> (8.8907, 7.5502)
  line L6 (13.6119, 19.5101) -> (13.7283, 12.5524)
  line L7 (5.0727, 27.7684) -> (13.6119, 19.5101)
  line L8 (8.165, 23.6131) -> (1.8571, 23.3937)
  line L9 (12.7805, 19.3079) -> (8.165, 23.6131)
  line L10 (13, 13) -> (12.7805, 19.3079)
  line L11 (8.6948, 8.3844) -> (13, 13)
  line L12 (2.3869, 8.165) -> (8.6948, 8.3844)
  line L13 (-2.2287, 12.4702) -> (2.3869, 8.165)
  line L14 (-2.4481, 18.7781) -> (-2.2287, 12.4702)
  line L15 (1.8571, 23.3937) -> (-2.4481, 18.7781)
  line L16 (1.8424, 24.4282) -> (8.357, 24.5921)
  point P17 (8.357, 24.5921)
  point P18 (1.8424, 24.4282)
  coincident L7 P17
  coincident L1 P18
extrude "Extrude28" cut sketch "Sketch38" profile of L1 L7 L16 against normal blind 15
extrude "Extrude29" add of existing geometry blind 4.5
delete_face "DeleteFace5"
move_face "MoveFace2"
move_face "MoveFace3"
extrude "Extrude30" cut of existing geometry blind -15
revolve "Revolve2" AlongAngle 360
move_face "MoveFace4"
move_face "MoveFace5"
extrude "Extrude38" cut sketch "Sketch14" + "Sketch15" profile of S1:L7 S1:L8 S1:L9 S1:L10 S1:L11 S1:L12 S1:L13 S1:L14 S1:L15 S1:L16 S1:L17 S1:L18 S1:L19 S1:L20 S1:L21 S1:L22 S1:L23 S1:L24 S1:L25 S1:L26 S1:L27 S1:L28 S1:L29 S1:L30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 blind -10
move_face "MoveFace6"
sketch "Sketch39" plane through (0, 0, 107.5) normal (0, 0, -1) x axis (1, 0, 0)
  circle C1 centre (-5.2725, 15.9) radius 8.3982
  circle C2 centre (10.0216, 108.1759) radius 0.2795
extrude "Extrude31" new body sketch "Sketch39" profile of C2 along normal blind 20
move_face "MoveFace7"
move_face "MoveFace8"
move_face "MoveFace9"
move_face "MoveFace10"
move "Move5"
move "Move6"
extrude "Extrude32" cut of existing geometry blind -5
move "Move7"
sketch "Sketch40" plane through (0, 0, 0) normal (0, 0, 1) x axis (1, 0, 0)
  line L1 (45, 55) -> (40, 55)
  line L2 (45, 52) -> (45, 55)
  line L3 (40, 52) -> (45, 52)
  line L4 (40, 55) -> (40, 52)
  horizontal L1
  vertical L2
  horizontal L3
  vertical L4
extrude "Extrude33" new body sketch "Sketch40" along normal blind 15
sketch "Sketch41" plane through (45, 0, 0) normal (1, 0, 0) x axis (0, 1, 0)
  line L1 (55, 0) -> (52, 0)
  line L2 (55, 15) -> (55, 0)
  line L3 (52, 15) -> (55, 15)
  line L4 (52, 0) -> (52, 15)
  line L5 (55, 15) -> (52, 15)
  line L6 (55, 13) -> (55, 15)
  line L7 (52, 13) -> (55, 13)
  line L8 (52, 15) -> (52, 13)
  point P8 (55, 13)
  point P5 (52, 15)
  point P6 (52, 15)
  horizontal L5
  vertical L6
  horizontal L7
  vertical L8
  coincident L2 P8
  coincident P5 P6
extrude "Extrude34" add sketch "Sketch41" profile of L2 L3 L4 L5 L6 L7 L8 along normal blind 1
sketch "Sketch42" plane through (0, 55, 0) normal (0, 1, 0) x axis (-1, 0, 0)
  line L1 (-40, 0) -> (-45, 0)
  line L2 (-40, 15) -> (-40, 0)
  line L3 (-46, 15) -> (-40, 15)
  line L4 (-46, 13) -> (-46, 15)
  line L5 (-45, 13) -> (-46, 13)
  line L6 (-45, 0) -> (-45, 13)
  line L7 (-40, 15) -> (-46, 15)
  line L8 (-40, 13) -> (-40, 15)
  line L9 (-46, 13) -> (-40, 13)
  line L10 (-46, 15) -> (-46, 13)
  point P10 (-40, 13)
  point P5 (-46, 15)
  point P8 (-46, 15)
  horizontal L7
  vertical L8
  horizontal L9
  vertical L10
  coincident L2 P10
  coincident P5 P8
extrude "Extrude35" add sketch "Sketch42" profile of L2 L3 L4 L5 L7 L8 L9 L10 along normal blind 1
sketch "Sketch43" plane through (0, 52, 0) normal (0, -1, 0) x axis (1, 0, 0)
  line L1 (45, 0) -> (40, 0)
  line L2 (45, 13) -> (45, 0)
  line L3 (46, 13) -> (45, 13)
  line L4 (46, 15) -> (46, 13)
  line L5 (40, 15) -> (46, 15)
  line L6 (40, 0) -> (40, 15)
move "Move8" TranslateX 0 TranslateY 70 TranslateZ 0
sketch "Sketch44" plane through (0, 122, 0) normal (0, -1, 0) x axis (1, 0, 0)
  line L1 (45, 0) -> (40, 0)
  line L2 (45, 13) -> (45, 0)
  line L3 (46, 13) -> (45, 13)
  line L4 (46, 15) -> (46, 13)
  line L5 (40, 15) -> (46, 15)
  line L6 (40, 0) -> (40, 15)
move "Move9" TranslateX -3 TranslateY -100 TranslateZ 60
sketch "Sketch45" plane through (37, 0, 0) normal (-1, 0, 0) x axis (0, -1, 0)
  line L1 (-22, 60) -> (-25, 60)
  line L2 (-22, 75) -> (-22, 60)
  line L3 (-26, 75) -> (-22, 75)
  line L4 (-26, 73) -> (-26, 75)
  line L5 (-25, 73) -> (-26, 73)
  line L6 (-25, 60) -> (-25, 73)
  line L7 (-22, 75) -> (-26, 75)
  line L8 (-22, 73) -> (-22, 75)
  line L9 (-26, 73) -> (-22, 73)
  line L10 (-26, 75) -> (-26, 73)
  point P10 (-22, 73)
  point P5 (-26, 75)
  point P8 (-26, 75)
  horizontal L7
  vertical L8
  horizontal L9
  vertical L10
  coincident L2 P10
  coincident P5 P8
extrude "Extrude36" add sketch "Sketch45" profile of L2 L3 L4 L5 L7 L8 L9 L10 along normal blind 1
sketch "Sketch46" plane through (0, 22, 0) normal (0, -1, 0) x axis (1, 0, 0)
  line L1 (42, 60) -> (37, 60)
  line L2 (42, 73) -> (42, 60)
  line L3 (43, 73) -> (42, 73)
  line L4 (43, 75) -> (43, 73)
  line L5 (36, 75) -> (43, 75)
  line L6 (36, 73) -> (36, 75)
  line L7 (37, 73) -> (36, 73)
  line L8 (37, 60) -> (37, 73)
  line L9 (43, 75) -> (36, 75)
  line L10 (43, 73) -> (43, 75)
  line L11 (36, 73) -> (43, 73)
  line L12 (36, 75) -> (36, 73)
  point P5 (43, 73)
  point P12 (43, 73)
  point P7 (36, 75)
  point P10 (36, 75)
  horizontal L9
  vertical L10
  horizontal L11
  vertical L12
  coincident P5 P12
  coincident P7 P10
extrude "Extrude37" add sketch "Sketch46" profile of L3 L4 L5 L6 L7 L9 L10 L11 L12 along normal blind 1
move "Move10" TranslateX 0 TranslateY 0 TranslateZ 5
extrude "Extrude38" add of existing geometry blind 2
move "Move11" TranslateX -3 TranslateY 0 TranslateZ 0
mirror "Mirror1" mirrorStitchTolerance 0.1
move "Move12"
mirror "Mirror2" mirrorStitchTolerance 0.1
move "Move13"
move "Move14"
move_face "MoveFace11"
move "Move15"
mirror "Mirror3" mirrorStitchTolerance 0.1
move "Move16"
mirror "Mirror4" mirrorStitchTolerance 0.1
mirror "Mirror5" mirrorStitchTolerance 0.1
move "Move17"
mirror "Mirror6" mirrorStitchTolerance 0.1
move "Move18"
move "Move19"
move "Move20"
